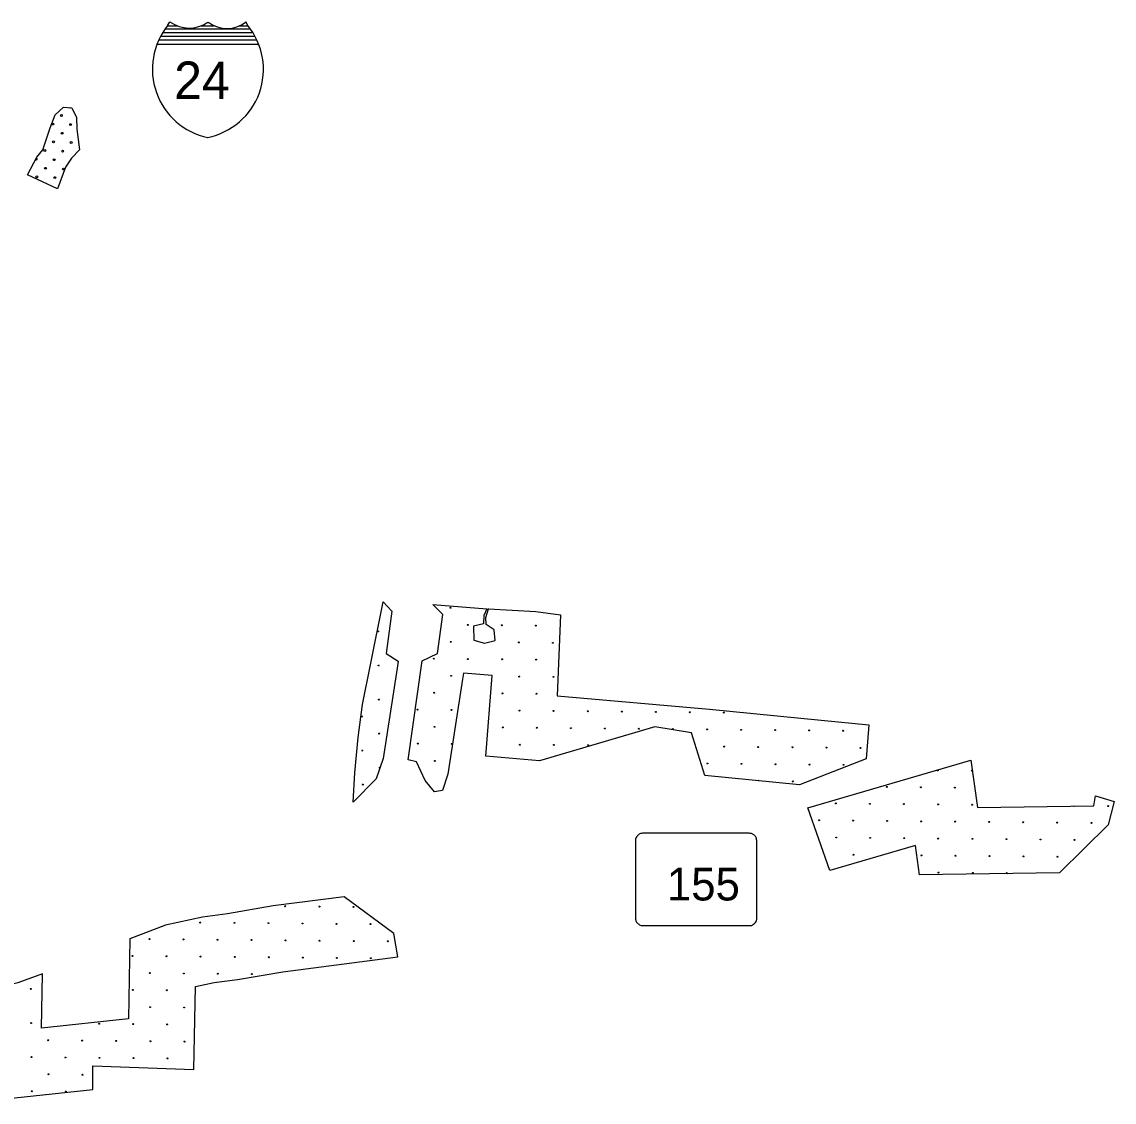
# Model space of a CAD drawing. Extents: x 1612280 to 1883141, y 560852 to 780851.
# Drawn here: x 1732699 to 1745034, y 691495 to 703687 of the extents above; entities that cross this region are included whole.
import ezdxf

# ---------------------------------------------------------------- set-up
doc = ezdxf.new("R2010")
doc.units = 0
for name, color, linetype in [('DESIGN - EROSION CONTROL - Devices', 7, 'Continuous'), ('DESIGN - ROW - Slope Lines', 7, 'Continuous'), ('DESIGN - SCRATCH - User 1', 7, 'Continuous'), ('DESIGN - TRAFFIC CONTROL PERMANENT - Pavement Marking Text', 7, 'Continuous'), ('SURVEY - DRAINAGE - Bridge Hydraulic Data with Text', 7, 'Continuous')]:
    doc.layers.add(name, color=color, linetype=linetype)

msp = doc.modelspace()

# ---------------------------------------------------------------- linework, layer by layer
at = {"layer": 'DESIGN - EROSION CONTROL - Devices'}
for centre in [(1737540, 697075), (1737540, 697075), (1736723, 696807), (1736723, 696807), (1737734, 696881), (1737734, 696881), (1738118, 696877), (1738118, 696877), (1738503, 696873), (1738503, 696873), (1737543, 696690), (1737543, 696690), (1738312, 696683), (1738312, 696683), (1738697, 696679), (1738697, 696679), (1736727, 696423), (1736727, 696423), (1737353, 696500), (1737353, 696500), (1737737, 696496), (1737737, 696496), (1738122, 696493), (1738122, 696493), (1738507, 696489), (1738507, 696489), (1737547, 696306), (1737547, 696306), (1738316, 696298), (1738316, 696298), (1738701, 696295), (1738701, 696295), (1737357, 696116), (1737357, 696116), (1738126, 696108), (1738126, 696108), (1738510, 696104), (1738510, 696104), (1736731, 696038), (1736731, 696038), (1736540, 695848), (1736540, 695848), (1737166, 695925), (1737166, 695925), (1737551, 695921), (1737551, 695921), (1738320, 695914), (1738320, 695914), (1738704, 695910), (1738704, 695910), (1739089, 695906), (1739089, 695906), (1739473, 695903), (1739473, 695903), (1739858, 695899), (1739858, 695899), (1740243, 695895), (1740243, 695895), (1740627, 695892), (1740627, 695892), (1737360, 695731), (1737360, 695731), (1738129, 695724), (1738129, 695724), (1738514, 695720), (1738514, 695720), (1738899, 695716), (1738899, 695716), (1739283, 695712), (1739283, 695712), (1739668, 695709), (1739668, 695709), (1740052, 695705), (1740052, 695705), (1740437, 695701), (1740437, 695701), (1740821, 695697), (1740821, 695697), (1741206, 695694), (1741206, 695694), (1741590, 695690), (1741590, 695690), (1741975, 695686), (1741975, 695686), (1736735, 695654), (1736735, 695654), (1736544, 695463), (1736544, 695463), (1737170, 695541), (1737170, 695541), (1737554, 695537), (1737554, 695537), (1738324, 695529), (1738324, 695529), (1738708, 695526), (1738708, 695526), (1739093, 695522), (1739093, 695522), (1740631, 695507), (1740631, 695507), (1741015, 695503), (1741015, 695503), (1741400, 695500), (1741400, 695500), (1741785, 695496), (1741785, 695496), (1742169, 695492), (1742169, 695492), (1737364, 695346), (1737364, 695346), (1740440, 695317), (1740440, 695317), (1740825, 695313), (1740825, 695313), (1741210, 695309), (1741210, 695309), (1741594, 695305), (1741594, 695305), (1741979, 695302), (1741979, 695302), (1743041, 695239), (1743041, 695239), (1743425, 695236), (1743425, 695236), (1736548, 695079), (1736548, 695079), (1741404, 695115), (1741404, 695115), (1742466, 695053), (1742466, 695053), (1742851, 695049), (1742851, 695049), (1743235, 695045), (1743235, 695045), (1741891, 694866), (1741891, 694866), (1742276, 694862), (1742276, 694862), (1742660, 694859), (1742660, 694859), (1743045, 694855), (1743045, 694855), (1743429, 694851), (1743429, 694851), (1744967, 694836), (1744967, 694836), (1741701, 694676), (1741701, 694676), (1742085, 694672), (1742085, 694672), (1742470, 694668), (1742470, 694668), (1742854, 694664), (1742854, 694664), (1743239, 694661), (1743239, 694661), (1743623, 694657), (1743623, 694657), (1744008, 694653), (1744008, 694653), (1744392, 694650), (1744392, 694650), (1744777, 694646), (1744777, 694646), (1741895, 694482), (1741895, 694482), (1742279, 694478), (1742279, 694478), (1742664, 694474), (1742664, 694474), (1743048, 694470), (1743048, 694470), (1743433, 694467), (1743433, 694467), (1743817, 694463), (1743817, 694463), (1744202, 694459), (1744202, 694459), (1744587, 694455), (1744587, 694455), (1742089, 694287), (1742089, 694287), (1742858, 694280), (1742858, 694280), (1743243, 694276), (1743243, 694276), (1743627, 694272), (1743627, 694272), (1744012, 694269), (1744012, 694269), (1744396, 694265), (1744396, 694265), (1743052, 694086), (1743052, 694086), (1743437, 694082), (1743437, 694082), (1735674, 693705), (1735674, 693705), (1736059, 693702), (1736059, 693702), (1736443, 693698), (1736443, 693698), (1734714, 693522), (1734714, 693522), (1735099, 693519), (1735099, 693519), (1735484, 693515), (1735484, 693515), (1735868, 693511), (1735868, 693511), (1736253, 693507), (1736253, 693507), (1736637, 693504), (1736637, 693504), (1734140, 693336), (1734140, 693336), (1734524, 693332), (1734524, 693332), (1734909, 693328), (1734909, 693328), (1735293, 693325), (1735293, 693325), (1735678, 693321), (1735678, 693321), (1736062, 693317), (1736062, 693317), (1736447, 693313), (1736447, 693313), (1736831, 693310), (1736831, 693310), (1733949, 693145), (1733949, 693145), (1734334, 693142), (1734334, 693142), (1734718, 693138), (1734718, 693138), (1735103, 693134), (1735103, 693134), (1735487, 693130), (1735487, 693130), (1735872, 693127), (1735872, 693127), (1736256, 693123), (1736256, 693123), (1736641, 693119), (1736641, 693119), (1734143, 692951), (1734143, 692951), (1734528, 692947), (1734528, 692947), (1734912, 692944), (1734912, 692944), (1735297, 692940), (1735297, 692940), (1732799, 692772), (1732799, 692772), (1733953, 692761), (1733953, 692761), (1734337, 692757), (1734337, 692757), (1734147, 692567), (1734147, 692567), (1734532, 692563), (1734532, 692563), (1732803, 692387), (1732803, 692387), (1733572, 692380), (1733572, 692380), (1733957, 692376), (1733957, 692376), (1734341, 692372), (1734341, 692372), (1732997, 692193), (1732997, 692193), (1733382, 692190), (1733382, 692190), (1733766, 692186), (1733766, 692186), (1734151, 692182), (1734151, 692182), (1734535, 692178), (1734535, 692178), (1732807, 692003), (1732807, 692003), (1733191, 691999), (1733191, 691999), (1733576, 691995), (1733576, 691995), (1733960, 691992), (1733960, 691992), (1734345, 691988), (1734345, 691988), (1733001, 691809), (1733001, 691809), (1733385, 691805), (1733385, 691805), (1732810, 691618), (1732810, 691618), (1733195, 691615), (1733195, 691615)]:
    msp.add_circle(centre, 5.28, dxfattribs=at)
for centre, start, end in [((1736738, 695269), 8.3066, 314.3193), ((1741019, 695119), 24.433, 144.3445), ((1744583, 694840), 241.2819, 300.4468), ((1743821, 694078), 301.339, 240.3896), ((1744206, 694075), 71.568, 110.1606)]:
    msp.add_arc(centre, 5.28, start, end, dxfattribs=at)
at = {"layer": 'DESIGN - ROW - Slope Lines'}
msp.add_line((1739627, 694428), (1739627, 693597), dxfattribs=at)
msp.add_line((1739627, 694428), (1739627, 693597), dxfattribs=at)
for points in [[(1741000, 694418), (1741000, 694426), (1740999, 694434), (1740998, 694448), (1740997, 694459), (1740995, 694470), (1740993, 694476), (1740990, 694482), (1740986, 694490), (1740980, 694497), (1740975, 694503), (1740970, 694508), (1740965, 694512), (1740958, 694516), (1740953, 694519), (1740945, 694523), (1740939, 694526), (1740932, 694527), (1740923, 694528), (1740914, 694529), (1740906, 694530), (1740893, 694530), (1740884, 694529), (1739727, 694530), (1739717, 694530), (1739707, 694529), (1739698, 694528), (1739689, 694526), (1739685, 694525), (1739677, 694522), (1739671, 694519), (1739666, 694515), (1739657, 694509), (1739651, 694503), (1739646, 694497), (1739642, 694492), (1739636, 694482), (1739633, 694475), (1739631, 694469), (1739630, 694466), (1739629, 694462), (1739628, 694455), (1739627, 694446), (1739627, 694438), (1739627, 694431), (1739627, 694413)], [(1741000, 694418), (1741000, 694426), (1740999, 694434), (1740998, 694448), (1740997, 694459), (1740995, 694470), (1740993, 694476), (1740990, 694482), (1740986, 694490), (1740980, 694497), (1740975, 694503), (1740970, 694508), (1740965, 694512), (1740958, 694516), (1740953, 694519), (1740945, 694523), (1740939, 694526), (1740932, 694527), (1740923, 694528), (1740914, 694529), (1740906, 694530), (1740893, 694530), (1740884, 694529), (1739727, 694530), (1739717, 694530), (1739707, 694529), (1739698, 694528), (1739689, 694526), (1739685, 694525), (1739677, 694522), (1739671, 694519), (1739666, 694515), (1739657, 694509), (1739651, 694503), (1739646, 694497), (1739642, 694492), (1739636, 694482), (1739633, 694475), (1739631, 694469), (1739630, 694466), (1739629, 694462), (1739628, 694455), (1739627, 694446), (1739627, 694438), (1739627, 694431), (1739627, 694413)], [(1740890, 693487), (1740910, 693488), (1740927, 693488), (1740938, 693490), (1740950, 693495), (1740961, 693502), (1740970, 693508), (1740978, 693516), (1740984, 693524), (1740990, 693534), (1740994, 693542), (1740997, 693549), (1740998, 693557), (1740999, 693565), (1740999, 693575), (1741000, 693598), (1741000, 694418)], [(1740890, 693487), (1740910, 693488), (1740927, 693488), (1740938, 693490), (1740950, 693495), (1740961, 693502), (1740970, 693508), (1740978, 693516), (1740984, 693524), (1740990, 693534), (1740994, 693542), (1740997, 693549), (1740998, 693557), (1740999, 693565), (1740999, 693575), (1741000, 693598), (1741000, 694418)], [(1739627, 693597), (1739627, 693588), (1739627, 693578), (1739628, 693568), (1739629, 693559), (1739631, 693550), (1739634, 693542), (1739637, 693535), (1739641, 693527), (1739647, 693520), (1739652, 693514), (1739660, 693507), (1739667, 693502), (1739675, 693497), (1739683, 693493), (1739692, 693490), (1739699, 693489), (1739714, 693488), (1739733, 693487), (1740890, 693487)], [(1739627, 693597), (1739627, 693588), (1739627, 693578), (1739628, 693568), (1739629, 693559), (1739631, 693550), (1739634, 693542), (1739637, 693535), (1739641, 693527), (1739647, 693520), (1739652, 693514), (1739660, 693507), (1739667, 693502), (1739675, 693497), (1739683, 693493), (1739692, 693490), (1739699, 693489), (1739714, 693488), (1739733, 693487), (1740890, 693487)]]:
    msp.add_lwpolyline(points, dxfattribs=at)
at = {"layer": 'DESIGN - SCRATCH - User 1'}
for points in [[(1732763, 701960), (1732867, 702159), (1732937, 702241), (1733019, 702492), (1733074, 702638), (1733169, 702724), (1733263, 702718), (1733318, 702608), (1733321, 702476), (1733349, 702244)], [(1732763, 701960), (1732867, 702159), (1732937, 702241), (1733019, 702492), (1733074, 702638), (1733169, 702724), (1733263, 702718), (1733318, 702608), (1733321, 702476), (1733349, 702244)], [(1733349, 702244), (1733260, 702147), (1733193, 702046), (1733102, 701802)], [(1733349, 702244), (1733260, 702147), (1733193, 702046), (1733102, 701802)], [(1733102, 701802), (1732763, 701960)], [(1733102, 701802), (1732763, 701960)], [(1736441, 694879), (1736458, 695210), (1736497, 695611), (1736547, 695982), (1736640, 696449), (1736779, 697141)], [(1736441, 694879), (1736458, 695210), (1736497, 695611), (1736547, 695982), (1736640, 696449), (1736779, 697141)], [(1736779, 697141), (1736877, 697036), (1736813, 696557)], [(1736779, 697141), (1736877, 697036), (1736813, 696557)], [(1737448, 695012), (1737360, 694996), (1737253, 695125), (1737157, 695335), (1737061, 695360), (1737221, 696477), (1737392, 696559), (1737453, 696998), (1737341, 697110)], [(1737448, 695012), (1737360, 694996), (1737253, 695125), (1737157, 695335), (1737061, 695360), (1737221, 696477), (1737392, 696559), (1737453, 696998), (1737341, 697110)], [(1737341, 697110), (1737950, 697061), (1737916, 696988), (1737911, 696893), (1737798, 696867), (1737804, 696710), (1737925, 696676), (1738044, 696704), (1738032, 696826), (1737943, 696884), (1737939, 696963), (1737967, 697064)], [(1737341, 697110), (1737950, 697061), (1737916, 696988), (1737911, 696893), (1737798, 696867), (1737804, 696710), (1737925, 696676), (1738044, 696704), (1738032, 696826), (1737943, 696884), (1737939, 696963), (1737967, 697064)], [(1737973, 697063), (1737967, 697064), (1738503, 697034), (1738780, 696994)], [(1737973, 697063), (1737967, 697064), (1738503, 697034), (1738780, 696994)], [(1738780, 696994), (1738746, 696082)], [(1738780, 696994), (1738746, 696082)], [(1736813, 696557), (1736949, 696470), (1736936, 696392), (1736779, 695374), (1736700, 695142), (1736441, 694879)], [(1736813, 696557), (1736949, 696470), (1736936, 696392), (1736779, 695374), (1736700, 695142), (1736441, 694879)], [(1737687, 696336), (1737676, 696270), (1737510, 695196), (1737448, 695012)], [(1737687, 696336), (1737676, 696270), (1737510, 695196), (1737448, 695012)], [(1738012, 696311), (1737687, 696336)], [(1738012, 696311), (1737687, 696336)], [(1737939, 695400), (1738012, 696311)], [(1737939, 695400), (1738012, 696311)], [(1738746, 696082), (1740463, 695930), (1741725, 695805), (1742265, 695752)], [(1738746, 696082), (1740463, 695930), (1741725, 695805), (1742265, 695752)], [(1739846, 695732), (1738544, 695347)], [(1739846, 695732), (1738544, 695347)], [(1740411, 695181), (1740261, 695662), (1739846, 695732)], [(1740411, 695181), (1740261, 695662), (1739846, 695732)], [(1742265, 695752), (1742235, 695368)], [(1742265, 695752), (1742235, 695368)], [(1738544, 695347), (1737939, 695400)], [(1738544, 695347), (1737939, 695400)], [(1742235, 695368), (1741481, 695076), (1740411, 695181)], [(1742235, 695368), (1741481, 695076), (1740411, 695181)], [(1741573, 694817), (1743416, 695355)], [(1741573, 694817), (1743416, 695355)], [(1743416, 695355), (1743489, 694819)], [(1743416, 695355), (1743489, 694819)], [(1743489, 694819), (1744806, 694839), (1744825, 694951)], [(1743489, 694819), (1744806, 694839), (1744825, 694951)], [(1744825, 694951), (1745034, 694888), (1744968, 694624), (1744415, 694083)], [(1744825, 694951), (1745034, 694888), (1744968, 694624), (1744415, 694083)], [(1741824, 694109), (1741573, 694817)], [(1741824, 694109), (1741573, 694817)], [(1742790, 694391), (1741824, 694109)], [(1742790, 694391), (1741824, 694109)], [(1742835, 694059), (1742790, 694391)], [(1742835, 694059), (1742790, 694391)], [(1744415, 694083), (1742835, 694059)], [(1744415, 694083), (1742835, 694059)], [(1736339, 693813), (1735536, 693709), (1735022, 693621), (1734740, 693584), (1734320, 693494), (1733920, 693339)], [(1736339, 693813), (1735536, 693709), (1735022, 693621), (1734740, 693584), (1734320, 693494), (1733920, 693339)], [(1736946, 693135), (1736898, 693398), (1736339, 693813)], [(1736946, 693135), (1736898, 693398), (1736339, 693813)], [(1733920, 693339), (1733903, 692435)], [(1733920, 693339), (1733903, 692435)], [(1734660, 692800), (1734869, 692845), (1735135, 692880), (1735647, 692967), (1736946, 693135)], [(1734660, 692800), (1734869, 692845), (1735135, 692880), (1735647, 692967), (1736946, 693135)], [(1732932, 692944), (1732653, 692843), (1732353, 692771), (1732151, 692728), (1731895, 692691)], [(1732932, 692944), (1732653, 692843), (1732353, 692771), (1732151, 692728), (1731895, 692691)], [(1732921, 692331), (1732932, 692944)], [(1732921, 692331), (1732932, 692944)], [(1734643, 691865), (1734660, 692800)], [(1734643, 691865), (1734660, 692800)], [(1733903, 692435), (1732921, 692331)], [(1733903, 692435), (1732921, 692331)], [(1733499, 691638), (1733499, 691906)], [(1733499, 691906), (1734643, 691865)], [(1733499, 691638), (1733499, 691906)], [(1733499, 691906), (1734643, 691865)], [(1732156, 691495), (1733499, 691638)], [(1732156, 691495), (1733499, 691638)]]:
    msp.add_lwpolyline(points, dxfattribs=at)
msp.add_circle((1733250, 702527), 10.6, dxfattribs=at)
msp.add_circle((1733250, 702527), 10.6, dxfattribs=at)
msp.add_arc((1733242, 702728), 10.6, 237.205, 295.405, dxfattribs=at)
at = {"layer": 'DESIGN - TRAFFIC CONTROL PERMANENT - Pavement Marking Text'}
for centre in [(1733145, 702631), (1733145, 702631), (1733048, 702534), (1733048, 702534), (1733153, 702429), (1733153, 702429), (1732959, 702235), (1732959, 702235), (1733056, 702332), (1733056, 702332), (1733160, 702228), (1733160, 702228), (1733257, 702325), (1733257, 702325), (1733063, 702131), (1733063, 702131), (1732966, 702034), (1732966, 702034), (1733168, 702026), (1733168, 702026), (1732869, 701937), (1732869, 701937), (1733071, 701929), (1733071, 701929)]:
    msp.add_circle(centre, 10.6, dxfattribs=at)
msp.add_arc((1732862, 702138), 10.6, 214.0533, 90.7517, dxfattribs=at)
at = {"layer": 'SURVEY - DRAINAGE - Bridge Hydraulic Data with Text'}
for p, q in [((1734319, 703609), (1735277, 703609)), ((1734319, 703609), (1735277, 703609)), ((1734345, 703642), (1734452, 703642)), ((1734345, 703642), (1734452, 703642)), ((1734721, 703642), (1734868, 703642)), ((1734721, 703642), (1734868, 703642)), ((1735154, 703642), (1735253, 703642)), ((1735154, 703642), (1735253, 703642)), ((1734249, 703485), (1735346, 703485)), ((1734249, 703485), (1735346, 703485)), ((1734270, 703526), (1735325, 703526)), ((1734270, 703526), (1735325, 703526)), ((1734296, 703565), (1735302, 703565)), ((1734296, 703565), (1735302, 703565)), ((1734228, 703435), (1735366, 703435)), ((1734228, 703435), (1735366, 703435))]:
    msp.add_line(p, q, dxfattribs=at)
for points in [[(1734349, 703648), (1734372, 703687)], [(1734349, 703648), (1734372, 703687)], [(1735250, 703645), (1735230, 703686)], [(1735250, 703645), (1735230, 703686)]]:
    msp.add_lwpolyline(points, dxfattribs=at)
for centre, radius, start, end in [((1734960, 703153), 787, 140.9901, 258.178), ((1734960, 703153), 787, 140.9901, 258.178), ((1734588, 703987), 370, 234.1647, 305.144), ((1734588, 703987), 370, 234.1647, 305.144), ((1734645, 703150), 782, 281.2226, 39.2925), ((1734645, 703150), 782, 281.2226, 39.2925), ((1735015, 703962), 350, 232.3625, 307.9876), ((1735015, 703962), 350, 232.3625, 307.9876)]:
    msp.add_arc(centre, radius, start, end, dxfattribs=at)

# ---------------------------------------------------------------- texts
at = {"layer": 'DESIGN - ROW - Slope Lines'}
msp.add_text('155', height=369.6, rotation=0.0012, dxfattribs=at).set_placement((1739983, 693771))
msp.add_text('155', height=369.6, rotation=0.0012, dxfattribs=at).set_placement((1739983, 693771))
at = {"layer": 'SURVEY - DRAINAGE - Bridge Hydraulic Data with Text'}
msp.add_text('24', height=422.4, rotation=0.0013, dxfattribs=at).set_placement((1734419, 702817))
msp.add_text('24', height=422.4, rotation=0.0013, dxfattribs=at).set_placement((1734419, 702817))

doc.saveas('drawing.dxf')
